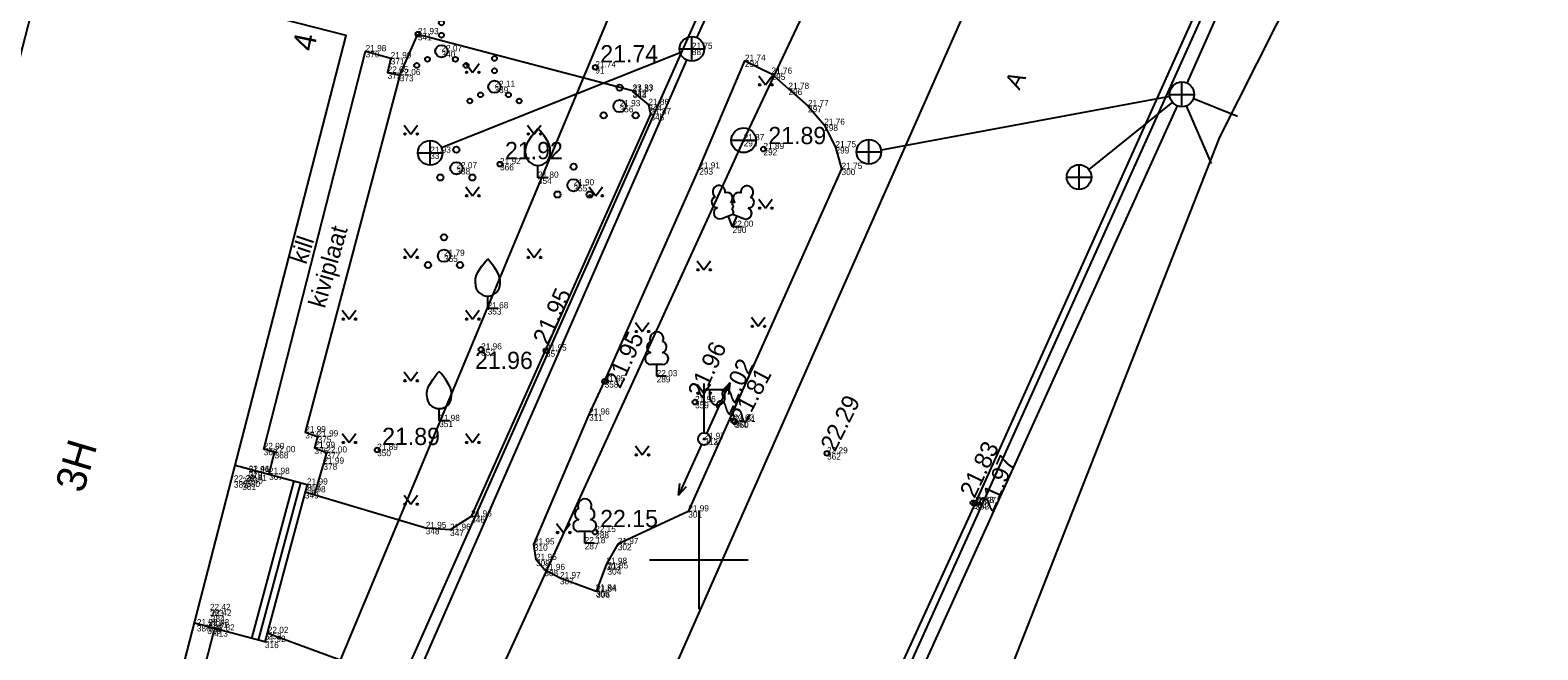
# Model space of a CAD drawing. Extents: x 714279 to 714471, y 6589851 to 6590083.
# Drawn here: x 714372.9 to 714434, y 6589996.4 to 6590021.5 of the extents above; entities that cross this region are included whole.
import ezdxf

# ---------------------------------------------------------------- set-up
doc = ezdxf.new("R2010")
doc.units = 0
for name, color, linetype in [('DTRASS', 7, 'Continuous'), ('HALJASTUS', 7, 'Continuous'), ('HOONE', 7, 'Continuous'), ('KKAEV', 7, 'Continuous'), ('KORGUS', 7, 'Continuous'), ('KPKAABEL', 7, 'Continuous'), ('KTRASS', 7, 'Continuous'), ('MOOTKORG', 7, 'Continuous'), ('MOOTMPUNKT', 7, 'Continuous'), ('MOOTPIIR', 7, 'Continuous'), ('MPOHULIIN', 7, 'Continuous'), ('PIIR', 7, 'Continuous'), ('POST', 7, 'Continuous'), ('PUU', 7, 'Continuous'), ('SITRASS', 7, 'Continuous'), ('SKKAEV', 7, 'Continuous'), ('SKTRASS', 7, 'Continuous'), ('TEE', 7, 'Continuous'), ('VKAEV', 7, 'Continuous'), ('VORK', 7, 'Continuous'), ('VTRASS', 7, 'Continuous')]:
    doc.layers.add(name, color=color, linetype=linetype)

# ---------------------------------------------------------------- blocks, each defined once
blk = doc.blocks.new('KAKAEV')
at = {"layer": 'KKAEV'}
for p, q in [((-1, 0), (1, 0)), ((0, -1), (0, 1))]:
    blk.add_line(p, q, dxfattribs=at)
blk.add_circle((0, 0), 1, dxfattribs=at)
blk = doc.blocks.new('RING02')
at = {"layer": 'KORGUS'}
blk.add_circle((0, 0), 0.2, dxfattribs=at)
blk = doc.blocks.new('LEHTP1')
at = {"layer": 'PUU'}
for p, q in [((0.48, 0.95), (-0.48, 0.95)), ((0, 0), (0, 0.95)), ((0.76, 0), (0, 0))]:
    blk.add_line(p, q, dxfattribs=at)
for centre, radius, start, end in [((-0.34, 2.35), 0.465, 109.0217, 253.1415), ((0, 3.04), 0.554, 332.5799, 207.4201), ((0.34, 2.35), 0.465, 286.8508, 70.9859), ((-0.47, 1.42), 0.475, 90.0016, 269.3953), ((0.47, 1.42), 0.475, 270.6047, 89.9984)]:
    blk.add_arc(centre, radius, start, end, dxfattribs=at)
blk = doc.blocks.new('LEHTP2')
at = {"layer": 'PUU'}
for p, q in [((-0.88, 0.67), (0.01, 1.02)), ((0, 0), (-0.35, 0.88)), ((0, 0), (0.36, 0.88)), ((0.76, 0), (0, 0)), ((0.01, 1.02), (0.89, 0.66))]:
    blk.add_line(p, q, dxfattribs=at)
blk.add_lwpolyline([(0.01, 2.01), (-0.03, 1.86), (-0.03, 1.82), (-0.01, 1.76), (0.03, 1.69), (0.04, 1.65), (0.01, 1.58), (-0.04, 1.48), (-0.05, 1.43), (-0.04, 1.4), (-0.02, 1.34), (0.05, 1.22), (0.06, 1.18), (0.05, 1.14), (0.02, 1.07), (0.01, 1.02)], dxfattribs=at)
for centre, radius, start, end in [((-1.11, 2.83), 0.512, 111.5027, 232.5173), ((-1.11, 2.83), 0.512, 350.4856, 111.5002), ((-0.44, 2.33), 0.448, 308.5041, 111.5725), ((0.48, 2.32), 0.45, 67.7016, 230.5126), ((1.16, 2.81), 0.512, 67.6168, 188.6314), ((1.16, 2.81), 0.512, 306.5997, 67.6143), ((-1.26, 2.01), 0.448, 111.4304, 274.4987), ((-1.05, 1.12), 0.475, 111.5014, 291.5004), ((0.01, 1.53), 0.475, 66.7655, 111.5015), ((1.07, 1.1), 0.475, 247.6166, 67.6155), ((1.29, 1.99), 0.448, 264.6183, 67.6866)]:
    blk.add_arc(centre, radius, start, end, dxfattribs=at)
blk = doc.blocks.new('BEPOST')
at = {"layer": 'POST'}
for radius in [0.5, 0.0467]:
    blk.add_circle((0, 0), radius, dxfattribs=at)
blk = doc.blocks.new('POINT_DISPLAY')
blk.add_line((0, 0), (0, 0))
blk = doc.blocks.new('VAPOST')
at = {"layer": 'POST'}
for p, q in [((0, 0.5), (0, 4.5)), ((0, 4), (2, 4)), ((0.45, 3.36), (0.45, 4)), ((1.68, 3.36), (1.68, 4))]:
    blk.add_line(p, q, dxfattribs=at)
blk.add_arc((1.07, 3.36), 0.613, 180, 0, dxfattribs=at)
blk.add_blockref('POINT_DISPLAY', (0, 0), dxfattribs=at)
blk = doc.blocks.new('PQQSAS')
at = {"layer": 'HALJASTUS'}
for centre, radius in [((0, 1.5), 0.25), ((0, 0), 0.5), ((-1.3, -0.75), 0.25), ((1.3, -0.75), 0.25)]:
    blk.add_circle(centre, radius, dxfattribs=at)
blk = doc.blocks.new('VQSA')
at = {"layer": 'HALJASTUS'}
for centre, radius in [((0, 2.3), 0.2), ((0, 1.3), 0.2), ((0, 0), 0.5), ((-2, -1.15), 0.2), ((-1.13, -0.65), 0.2), ((1.13, -0.65), 0.2), ((2, -1.15), 0.2)]:
    blk.add_circle(centre, radius, dxfattribs=at)
blk = doc.blocks.new('VILJA1')
at = {"layer": 'PUU'}
for p, q in [((0, 0), (0, 1)), ((0.8, 0), (0, 0))]:
    blk.add_line(p, q, dxfattribs=at)
for points in [[(-1, 2), (-1, 2.3), (-0.98, 2.43), (-0.91, 2.69), (-0.79, 2.93), (-0.5, 3.4), (-0.18, 3.81), (0, 4)], [(1, 2), (1, 2.3), (0.98, 2.43), (0.91, 2.69), (0.79, 2.93), (0.5, 3.4), (0.18, 3.81), (0, 4)]]:
    blk.add_lwpolyline(points, dxfattribs=at)
blk.add_arc((0, 2), 1, 180, 0, dxfattribs=at)
blk = doc.blocks.new('RING02_1')
at = {"layer": 'KORGUS'}
blk.add_circle((0, 0), 0.2, dxfattribs=at)
blk = doc.blocks.new('RING02_2')
at = {"layer": 'KORGUS'}
blk.add_circle((0, 0), 0.2, dxfattribs=at)
blk = doc.blocks.new('MPSUUN')
at = {"layer": 'MPOHULIIN'}
for p, q in [((0.5, 0), (5, 0)), ((5, 0), (4.1, 0.3)), ((5, 0), (4.1, -0.3))]:
    blk.add_line(p, q, dxfattribs=at)
blk.add_blockref('POINT_DISPLAY', (0, 0), dxfattribs=at)
blk = doc.blocks.new('VEKAEV')
at = {"layer": 'VKAEV'}
blk.add_line((-1, 0), (1, 0), dxfattribs=at)
blk.add_circle((0, 0), 1, dxfattribs=at)
blk = doc.blocks.new('MURU_1')
at = {"layer": 'HALJASTUS'}
for p, q in [((-0.93, 1.21), (0, 0)), ((0, 0), (0.89, 1.21))]:
    blk.add_line(p, q, dxfattribs=at)
for centre in [(-0.8, 0), (0.86, 0)]:
    blk.add_circle(centre, 0.11, dxfattribs=at)

msp = doc.modelspace()

# ---------------------------------------------------------------- linework, layer by layer
at = {"layer": 'DTRASS'}
for points in [[(714419.752, 6590018.407), (714420.767, 6590016.07)], [(714420.094, 6590018.692), (714421.838, 6590017.985)]]:
    msp.add_lwpolyline(points, dxfattribs=at)
at = {"layer": 'HOONE'}
for points in [[(714368.084, 6590003.497), (714362.833, 6589983.153), (714366.948, 6589982.091), (714366.479, 6589980.273), (714368.704, 6589979.699), (714369.168, 6589981.497), (714375.054, 6589979.978), (714385.707, 6590021.254), (714379.88, 6590022.758), (714380.346, 6590024.563), (714378.09, 6590025.145), (714377.63, 6590023.366), (714373.521, 6590024.426), (714369.05, 6590007.103), (714363.815, 6590008.455), (714364.534, 6590011.243), (714349.394, 6590015.151), (714346.235, 6590002.913), (714361.396, 6589999), (714362.901, 6590004.835), (714368.084, 6590003.497)], [(714381.211, 6590003.835), (714384.124, 6590003.056), (714382.417, 6589996.677), (714379.561, 6589997.441)], [(714383.583, 6590003.201), (714381.876, 6589996.822)], [(714383.854, 6590003.128), (714382.147, 6589996.749)]]:
    msp.add_lwpolyline(points, dxfattribs=at)
at = {"layer": 'KORGUS'}
msp.add_circle((714388.618, 6590021.311), 0.1, dxfattribs=at)
at = {"layer": 'KPKAABEL'}
msp.add_lwpolyline([(714396.776, 6589958.555), (714410.513, 6589990.138), (714421.117, 6590017.14), (714434.01, 6590042.696)], dxfattribs=at)
at = {"layer": 'KTRASS'}
for points in [[(714399.928, 6590021.168), (714409.418, 6590042.018)], [(714380.6, 6589977.024), (714399.521, 6590020.255)], [(714399.249, 6590020.548), (714389.579, 6590016.701)]]:
    msp.add_lwpolyline(points, dxfattribs=at)
at = {"layer": 'MOOTPIIR'}
msp.add_lwpolyline([(714325.392, 6590064.148), (714418.405, 6590047.495), (714428.059, 6590039.059), (714392.952, 6589961.13), (714372.822, 6589966.903), (714302.696, 6589965.199), (714319.941, 6590042.637), (714325.392, 6590064.148)], dxfattribs=at)
at = {"layer": 'PIIR'}
msp.add_lwpolyline([(714313.433, 6589985.9), (714378.228, 6589973.152), (714405.629, 6590034.791), (714332.408, 6590052.951), (714332.595, 6590052.951)], dxfattribs=at)
at = {"layer": 'SITRASS'}
msp.add_lwpolyline([(714403.003, 6590037.966), (714373.288, 6589966.766)], dxfattribs=at)
at = {"layer": 'SKKAEV'}
for p, q in [((714419.083, 6590018.872), (714420.083, 6590018.872)), ((714419.583, 6590018.372), (714419.583, 6590019.372)), ((714406.895, 6590016.04), (714406.895, 6590017.04)), ((714406.395, 6590016.54), (714407.395, 6590016.54)), ((714415.415, 6590015.02), (714415.415, 6590016.02)), ((714414.915, 6590015.52), (714415.915, 6590015.52))]:
    msp.add_line(p, q, dxfattribs=at)
for centre in [(714419.583, 6590018.872), (714406.895, 6590016.54), (714415.415, 6590015.52)]:
    msp.add_circle(centre, 0.5, dxfattribs=at)
at = {"layer": 'SKTRASS'}
for points in [[(714419.795, 6590019.325), (714428.522, 6590038.973)], [(714419.091, 6590018.783), (714407.392, 6590016.607)], [(714404.146, 6589984.744), (714419.399, 6590018.407)], [(714419.198, 6590018.553), (714415.808, 6590015.829)]]:
    msp.add_lwpolyline(points, dxfattribs=at)
at = {"layer": 'TEE'}
for points in [[(714428.059, 6590039.059), (714427.912, 6590038.899), (714421.383, 6590024.973), (714411.21, 6590002.295), (714399.51, 6589976.749), (714392.577, 6589961.261), (714392.577, 6589961.261)], [(714388.618, 6590021.311), (714397.317, 6590019.024), (714397.328, 6590018.972), (714397.958, 6590018.442), (714398.041, 6590018.065), (714390.775, 6590001.761), (714389.92, 6590001.218), (714388.935, 6590001.294), (714384.038, 6590002.741)], [(714387.883, 6590019.652), (714387.883, 6590019.652), (714388.618, 6590021.311)], [(714382.584, 6590003.491), (714382.81, 6590004.367), (714382.368, 6590004.496), (714386.498, 6590020.618), (714387.515, 6590020.334), (714387.39, 6590019.753), (714387.883, 6590019.652), (714384.05, 6590005.176), (714384.551, 6590005.008), (714384.423, 6590004.545), (714384.908, 6590004.355), (714384.786, 6590003.903), (714384.41, 6590002.642)], [(714395.842, 6589998.716), (714394.376, 6589999.261), (714393.742, 6589999.593), (714393.405, 6589999.999), (714393.318, 6590000.628), (714395.556, 6590005.893), (714396.186, 6590007.236), (714400.021, 6590015.872), (714401.872, 6590020.232), (714402.948, 6590019.709), (714403.636, 6590019.092), (714404.431, 6590018.398), (714405.086, 6590017.639), (714405.541, 6590016.725), (714405.789, 6590015.848), (714399.574, 6590001.968), (714396.72, 6590000.646), (714396.258, 6589999.841)], [(714396.258, 6589999.841), (714395.842, 6589998.716)], [(714375.863, 6589979.673), (714380.355, 6589997.141)], [(714382.534, 6589997.039), (714386.904, 6589995.418), (714387.333, 6589994.181), (714380.429, 6589978.462)]]:
    msp.add_lwpolyline(points, dxfattribs=at)
at = {"layer": 'VORK'}
for p, q in [((714400, 6590002), (714400, 6589998)), ((714398, 6590000), (714402, 6590000))]:
    msp.add_line(p, q, dxfattribs=at)
at = {"layer": 'VTRASS'}
for points in [[(714378.183, 6589965.384), (714401.816, 6590016.993), (714414.734, 6590044.36), (714416.367, 6590047.881)], [(714384.776, 6589963.41), (714420.935, 6590045.157)]]:
    msp.add_lwpolyline(points, dxfattribs=at)

# ---------------------------------------------------------------- block references
at = {"layer": 'HALJASTUS'}
for name, p, xscale, yscale in [('VQSA', (714389.571, 6590020.618), 0.5, 0.5), ('MURU_1', (714390.832, 6590019.761), 0.3, 0.3), ('VQSA', (714391.72, 6590019.177), 0.5, 0.5), ('MURU_1', (714402.711, 6590019.259), 0.3, 0.3), ('PQQSAS', (714396.793, 6590018.393), 0.5, 0.5), ('MURU_1', (714388.332, 6590017.261), 0.3, 0.3), ('MURU_1', (714393.332, 6590017.261), 0.3, 0.3), ('PQQSAS', (714390.177, 6590015.876), 0.5, 0.5), ('PQQSAS', (714394.924, 6590015.187), 0.5, 0.5), ('MURU_1', (714390.832, 6590014.761), 0.3, 0.3), ('MURU_1', (714395.832, 6590014.761), 0.3, 0.3), ('MURU_1', (714402.711, 6590014.259), 0.3, 0.3), ('PQQSAS', (714389.675, 6590012.328), 0.5, 0.5), ('MURU_1', (714388.332, 6590012.261), 0.3, 0.3), ('MURU_1', (714393.332, 6590012.261), 0.3, 0.3), ('MURU_1', (714400.211, 6590011.759), 0.3, 0.3), ('MURU_1', (714385.832, 6590009.761), 0.3, 0.3), ('MURU_1', (714390.832, 6590009.761), 0.3, 0.3), ('MURU_1', (714397.711, 6590009.259), 0.3, 0.3), ('MURU_1', (714402.41, 6590009.471), 0.3, 0.3), ('MURU_1', (714388.332, 6590007.261), 0.3, 0.3), ('MURU_1', (714400.211, 6590006.759), 0.3, 0.3), ('MURU_1', (714385.832, 6590004.761), 0.3, 0.3), ('MURU_1', (714390.832, 6590004.761), 0.3, 0.3), ('MURU_1', (714397.711, 6590004.259), 0.3, 0.3), ('MURU_1', (714388.332, 6590002.261), 0.3, 0.3), ('MURU_1', (714394.516, 6590001.11), 0.3, 0.3)]:
    msp.add_blockref(name, p, dxfattribs=dict(at, xscale=xscale, yscale=yscale))
at = {"layer": 'KKAEV', "xscale": 0.5, "yscale": 0.5}
for p in [(714399.721, 6590020.713), (714389.115, 6590016.503)]:
    msp.add_blockref('KAKAEV', p, dxfattribs=at)
at = {"layer": 'KORGUS', "xscale": 0.5, "yscale": 0.5}
for name, p in [('RING02', (714395.809, 6590019.966)), ('RING02', (714402.623, 6590016.653)), ('RING02', (714391.947, 6590016.042)), ('RING02', (714391.179, 6590008.532)), ('RING02_1', (714393.808, 6590008.484)), ('RING02_1', (714396.186, 6590007.236)), ('RING02', (714399.852, 6590006.397)), ('RING02_1', (714401.414, 6590005.646)), ('RING02_2', (714401.462, 6590005.598)), ('RING02', (714386.967, 6590004.458)), ('RING02_1', (714405.2, 6590004.321)), ('RING02_2', (714411.121, 6590002.315)), ('RING02_1', (714411.21, 6590002.295)), ('RING02', (714395.803, 6590001.129))]:
    msp.add_blockref(name, p, dxfattribs=at)
at = {"layer": 'MPOHULIIN', "xscale": 0.49999999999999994}
for yscale, rotation in [(0.5000000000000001, 65.5926653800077), (0.5, -114.57391464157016)]:
    msp.add_blockref('MPSUUN', (714400.22, 6590004.904), dxfattribs=dict(at, yscale=yscale, rotation=rotation))
at = {"layer": 'POST', "xscale": 0.5, "yscale": 0.5}
for name in ['VAPOST', 'BEPOST']:
    msp.add_blockref(name, (714400.22, 6590004.904), dxfattribs=at)
at = {"layer": 'PUU', "xscale": 0.5, "yscale": 0.5}
for name, p in [('VILJA1', (714393.482, 6590015.492)), ('LEHTP2', (714401.373, 6590013.504)), ('VILJA1', (714391.445, 6590010.198)), ('LEHTP1', (714398.296, 6590007.448)), ('VILJA1', (714389.48, 6590005.633)), ('LEHTP1', (714395.378, 6590000.679))]:
    msp.add_blockref(name, p, dxfattribs=at)
at = {"layer": 'VKAEV', "xscale": 0.5, "yscale": 0.5}
msp.add_blockref('VEKAEV', (714401.82, 6590017.01), dxfattribs=at)

# ---------------------------------------------------------------- texts
at = {"layer": 'HOONE'}
for s, height, rotation, p in [('4', 0.9, 78.31506, (714384.401, 6590020.581)), ('3H', 1.2, 73.44903, (714375.046, 6590002.67))]:
    msp.add_text(s, height=height, rotation=rotation, dxfattribs=at).set_placement(p)
at = {"layer": 'KORGUS'}
for s, p in [('21.74', (714396.009, 6590020.166)), ('21.89', (714402.823, 6590016.853)), ('21.92', (714392.147, 6590016.242)), ('21.96', (714390.932, 6590007.74)), ('21.89', (714387.167, 6590004.658)), ('22.15', (714396.003, 6590001.329))]:
    msp.add_text(s, height=0.7, dxfattribs=at).set_placement(p)
for s, rotation, p in [('21.95', 65.44127, (714393.882, 6590008.673)), ('21.95', 65.34769, (714396.815, 6590006.91)), ('21.96', 65.0273, (714400.155, 6590006.51)), ('22.02', 64.57803, (714401.243, 6590005.817)), ('21.81', 62.17516, (714401.88, 6590005.47)), ('22.29', 63.68557, (714405.523, 6590004.345)), ('21.83', 64.56491, (714411.179, 6590002.47)), ('21.97', 66.31087, (714411.924, 6590001.892))]:
    msp.add_text(s, height=0.7, rotation=rotation, dxfattribs=at).set_placement(p)
at = {"layer": 'MOOTKORG'}
for s, p in [('21.93', (714388.618, 6590021.311)), ('21.98', (714386.498, 6590020.618)), ('22.07', (714389.571, 6590020.618)), ('21.75', (714399.721, 6590020.713)), ('22.05', (714387.39, 6590019.753)), ('21.99', (714387.515, 6590020.334)), ('21.74', (714395.809, 6590019.966)), ('21.74', (714401.872, 6590020.232)), ('22.06', (714387.883, 6590019.652)), ('22.11', (714391.72, 6590019.177)), ('21.76', (714402.948, 6590019.709)), ('23.33', (714397.317, 6590019.024)), ('21.87', (714397.328, 6590018.972)), ('21.78', (714403.636, 6590019.092)), ('21.93', (714396.793, 6590018.393)), ('21.86', (714397.958, 6590018.442)), ('21.87', (714398.041, 6590018.065)), ('21.77', (714404.431, 6590018.398)), ('21.76', (714405.086, 6590017.639)), ('21.87', (714401.82, 6590017.01)), ('21.75', (714405.541, 6590016.725)), ('21.93', (714389.115, 6590016.503)), ('21.89', (714402.623, 6590016.653)), ('22.07', (714390.177, 6590015.876)), ('21.92', (714391.947, 6590016.042)), ('21.80', (714393.482, 6590015.492)), ('21.91', (714400.021, 6590015.872)), ('21.75', (714405.789, 6590015.848)), ('21.90', (714394.924, 6590015.187)), ('22.00', (714401.373, 6590013.504)), ('21.79', (714389.675, 6590012.328)), ('21.68', (714391.445, 6590010.198)), ('21.96', (714391.179, 6590008.532)), ('21.95', (714393.808, 6590008.484)), ('21.95', (714396.186, 6590007.236)), ('22.03', (714398.296, 6590007.448)), ('21.96', (714399.852, 6590006.397)), ('21.96', (714395.556, 6590005.893)), ('21.99', (714384.05, 6590005.176)), ('21.98', (714389.48, 6590005.633)), ('22.02', (714401.414, 6590005.646)), ('21.81', (714401.462, 6590005.598)), ('22.00', (714382.368, 6590004.496)), ('21.99', (714384.423, 6590004.545)), ('21.99', (714384.551, 6590005.008)), ('21.97', (714400.22, 6590004.904)), ('21.97', (714400.22, 6590004.904)), ('22.00', (714382.81, 6590004.367)), ('21.99', (714384.786, 6590003.903)), ('22.00', (714384.908, 6590004.355)), ('21.89', (714386.967, 6590004.458)), ('22.29', (714405.2, 6590004.321)), ('21.96', (714381.757, 6590003.56)), ('22.41', (714381.758, 6590003.572)), ('21.98', (714382.584, 6590003.491)), ('22.38', (714381.159, 6590003.178)), ('22.40', (714381.498, 6590003.09)), ('22.41', (714381.658, 6590003.203)), ('21.98', (714384.038, 6590002.741)), ('21.99', (714384.124, 6590003.056)), ('21.83', (714411.121, 6590002.315)), ('21.97', (714411.21, 6590002.295)), ('21.96', (714390.775, 6590001.761)), ('21.99', (714399.574, 6590001.968)), ('21.95', (714388.935, 6590001.294)), ('21.96', (714389.92, 6590001.218)), ('22.15', (714395.803, 6590001.129)), ('21.95', (714393.318, 6590000.628)), ('22.18', (714395.378, 6590000.679)), ('21.97', (714396.72, 6590000.646)), ('21.95', (714393.405, 6589999.999)), ('21.96', (714393.742, 6589999.593)), ('21.98', (714396.258, 6589999.841)), ('21.85', (714396.3, 6589999.656)), ('21.97', (714394.376, 6589999.261)), ('21.84', (714395.822, 6589998.764)), ('21.84', (714395.842, 6589998.716)), ('22.42', (714380.187, 6589997.969)), ('21.95', (714379.657, 6589997.352)), ('21.81', (714380.083, 6589997.252)), ('22.43', (714380.131, 6589997.351)), ('22.42', (714380.226, 6589997.735)), ('21.82', (714380.355, 6589997.141)), ('21.92', (714382.417, 6589996.677)), ('22.02', (714382.534, 6589997.039))]:
    msp.add_text(s, height=0.25, dxfattribs=at).set_placement(p)
at = {"layer": 'MOOTMPUNKT'}
for s, p in [('341', (714388.618, 6590021.061)), ('370', (714386.498, 6590020.368)), ('340', (714389.571, 6590020.368)), ('88', (714399.721, 6590020.463)), ('371', (714387.515, 6590020.084)), ('294', (714401.872, 6590019.982)), ('372', (714387.39, 6590019.503)), ('373', (714387.883, 6590019.402)), ('91', (714395.809, 6590019.716)), ('295', (714402.948, 6590019.459)), ('339', (714391.72, 6590018.927)), ('342', (714397.317, 6590018.774)), ('343', (714397.328, 6590018.722)), ('296', (714403.636, 6590018.842)), ('356', (714396.793, 6590018.143)), ('344', (714397.958, 6590018.192)), ('297', (714404.431, 6590018.148)), ('345', (714398.041, 6590017.815)), ('298', (714405.086, 6590017.389)), ('291', (714401.82, 6590016.76)), ('337', (714389.115, 6590016.253)), ('292', (714402.623, 6590016.403)), ('299', (714405.541, 6590016.475)), ('338', (714390.177, 6590015.626)), ('366', (714391.947, 6590015.792)), ('293', (714400.021, 6590015.622)), ('300', (714405.789, 6590015.598)), ('354', (714393.482, 6590015.242)), ('355', (714394.924, 6590014.937)), ('290', (714401.373, 6590013.254)), ('365', (714389.675, 6590012.078)), ('353', (714391.445, 6590009.948)), ('352', (714391.179, 6590008.282)), ('357', (714393.808, 6590008.234)), ('358', (714396.186, 6590006.986)), ('289', (714398.296, 6590007.198)), ('359', (714399.852, 6590006.147)), ('351', (714389.48, 6590005.383)), ('311', (714395.556, 6590005.643)), ('361', (714401.414, 6590005.396)), ('360', (714401.462, 6590005.348)), ('374', (714384.05, 6590004.926)), ('375', (714384.551, 6590004.758)), ('312', (714400.22, 6590004.654)), ('313', (714400.22, 6590004.654)), ('369', (714382.368, 6590004.246)), ('368', (714382.81, 6590004.117)), ('376', (714384.423, 6590004.295)), ('377', (714384.908, 6590004.105)), ('350', (714386.967, 6590004.208)), ('362', (714405.2, 6590004.071)), ('318', (714381.757, 6590003.31)), ('379', (714381.758, 6590003.322)), ('367', (714382.584, 6590003.241)), ('378', (714384.786, 6590003.653)), ('382', (714381.159, 6590002.928)), ('381', (714381.498, 6590002.84)), ('380', (714381.658, 6590002.953)), ('317', (714384.124, 6590002.806)), ('349', (714384.038, 6590002.491)), ('364', (714411.121, 6590002.065)), ('363', (714411.21, 6590002.045)), ('346', (714390.775, 6590001.511)), ('301', (714399.574, 6590001.718)), ('348', (714388.935, 6590001.044)), ('347', (714389.92, 6590000.968)), ('288', (714395.803, 6590000.879)), ('310', (714393.318, 6590000.378)), ('287', (714395.378, 6590000.429)), ('302', (714396.72, 6590000.396)), ('309', (714393.405, 6589999.749)), ('303', (714396.258, 6589999.591)), ('308', (714393.742, 6589999.343)), ('307', (714394.376, 6589999.011)), ('304', (714396.3, 6589999.406)), ('305', (714395.822, 6589998.514)), ('306', (714395.842, 6589998.466)), ('383', (714380.187, 6589997.719)), ('384', (714380.226, 6589997.485)), ('386', (714379.657, 6589997.102)), ('319', (714380.083, 6589997.002)), ('385', (714380.131, 6589997.101)), ('413', (714380.355, 6589996.891)), ('253', (714382.534, 6589996.789)), ('316', (714382.417, 6589996.427))]:
    msp.add_text(s, height=0.25, dxfattribs=at).set_placement(p)
at = {"layer": 'TEE'}
for s, rotation, p in [('A', 63.06115, (714412.996, 6590019.011)), ('kiviplaat', 73.81677, (714384.837, 6590010.169)), ('kill', 71.57175, (714384.081, 6590011.943))]:
    msp.add_text(s, height=0.7, rotation=rotation, dxfattribs=at).set_placement(p)

doc.saveas('drawing.dxf')
